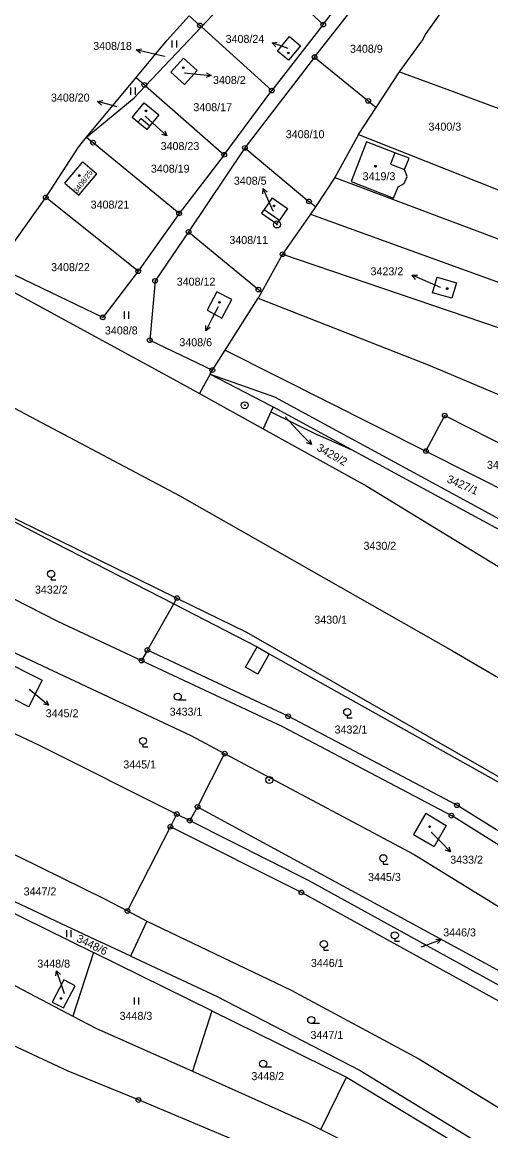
# Model space of a CAD drawing. Extents: x -593183 to -588034, y -1130415 to -1124994.
# Drawn here: x -592629 to -592529.4, y -1128913.5 to -1128677.9 of the extents above; entities that cross this region are included whole.
import ezdxf

# ---------------------------------------------------------------- set-up
doc = ezdxf.new("R2010")
doc.units = 0
for name, color, linetype in [('Vrstva 1', 7, 'Continuous'), ('Vrstva 16', 7, 'Continuous'), ('Vrstva 18', 7, 'Continuous'), ('Vrstva 19', 7, 'Continuous'), ('Vrstva 24', 7, 'Continuous'), ('Vrstva 25', 7, 'Continuous'), ('Vrstva 4', 7, 'Continuous')]:
    doc.layers.add(name, color=color, linetype=linetype)

msp = doc.modelspace()

# ---------------------------------------------------------------- linework, layer by layer
at = {"layer": 'Vrstva 1'}
for p, q in [((-592565.01, -1128678.4), (-592551.77, -1128661.06)), ((-592566.85, -1128685.3), (-592549.6, -1128663.24)), ((-592590.91, -1128678.86), (-592578.64, -1128665.83)), ((-592578.64, -1128665.83), (-592565.01, -1128678.4)), ((-592537.4, -1128672.05), (-592543.19, -1128680.31)), ((-592598.22, -1128681.71), (-592593.48, -1128676.53)), ((-592593.48, -1128676.53), (-592591.22, -1128678.58)), ((-592602.77, -1128691.45), (-592590.91, -1128678.86)), ((-592591.22, -1128678.58), (-592590.91, -1128678.86)), ((-592590.91, -1128678.86), (-592575.96, -1128692.42)), ((-592565.01, -1128678.4), (-592575.96, -1128692.42)), ((-592604.81, -1128689.67), (-592598.22, -1128681.71)), ((-592574.77, -1128684.08), (-592572.18, -1128680.97)), ((-592572.18, -1128680.97), (-592569.85, -1128682.91)), ((-592548.82, -1128688.45), (-592544.06, -1128681.91)), ((-592543.19, -1128680.31), (-592544.06, -1128681.91)), ((-592572.42, -1128685.98), (-592574.77, -1128684.08)), ((-592569.85, -1128682.91), (-592572.42, -1128685.98)), ((-592597.4, -1128688.53), (-592594.74, -1128685.56)), ((-592594.74, -1128685.56), (-592591.84, -1128688.16)), ((-592566.85, -1128685.3), (-592581.66, -1128704.6)), ((-592566.85, -1128685.3), (-592555.46, -1128694.64)), ((-592594.5, -1128691.13), (-592597.4, -1128688.53)), ((-592591.84, -1128688.16), (-592594.5, -1128691.13)), ((-592553.77, -1128696.03), (-592548.82, -1128688.45)), ((-592548.82, -1128688.45), (-592538.73, -1128692.12)), ((-592615.32, -1128702.35), (-592604.81, -1128689.67)), ((-592604.81, -1128689.67), (-592603.04, -1128691.22)), ((-592603.04, -1128691.22), (-592602.77, -1128691.45)), ((-592602.77, -1128691.45), (-592605.17, -1128694)), ((-592602.77, -1128691.45), (-592586.05, -1128706.06)), ((-592586.05, -1128706.06), (-592575.96, -1128692.42)), ((-592538.73, -1128692.12), (-592523.45, -1128697.86)), ((-592615.32, -1128702.35), (-592605.17, -1128694)), ((-592605.62, -1128698.13), (-592603.06, -1128695.05)), ((-592603.06, -1128695.05), (-592599.98, -1128697.61)), ((-592557.5, -1128701.77), (-592553.77, -1128696.03)), ((-592555.46, -1128694.64), (-592553.77, -1128696.03)), ((-592604.39, -1128699.15), (-592605.62, -1128698.13)), ((-592599.98, -1128697.61), (-592601.9, -1128699.92)), ((-592602.54, -1128700.69), (-592604.39, -1128699.15)), ((-592601.9, -1128699.92), (-592602.54, -1128700.69)), ((-592617.04, -1128704.43), (-592615.32, -1128702.35)), ((-592615.32, -1128702.35), (-592613.92, -1128703.5)), ((-592557.5, -1128701.77), (-592562.55, -1128710.89)), ((-592557.5, -1128701.77), (-592539.83, -1128708.8)), ((-592624, -1128715.14), (-592617.04, -1128704.43)), ((-592595.67, -1128718.55), (-592613.92, -1128703.5)), ((-592581.66, -1128704.6), (-592593.65, -1128722.45)), ((-592581.66, -1128704.6), (-592568.05, -1128715.98)), ((-592555.8, -1128703.33), (-592559.1, -1128711.75)), ((-592549.82, -1128705.64), (-592555.8, -1128703.33)), ((-592619.95, -1128712.12), (-592616.12, -1128707.6)), ((-592616.12, -1128707.6), (-592613.12, -1128710.14)), ((-592586.05, -1128706.06), (-592595.67, -1128718.55)), ((-592546.78, -1128706.8), (-592549.82, -1128705.64)), ((-592547.73, -1128709.22), (-592546.78, -1128706.8)), ((-592616.97, -1128714.68), (-592613.12, -1128710.14)), ((-592547.2, -1128710.68), (-592547.73, -1128709.22)), ((-592539.83, -1128708.8), (-592506.46, -1128722.05)), ((-592619.95, -1128712.12), (-592616.97, -1128714.68)), ((-592562.55, -1128710.89), (-592566.68, -1128717.13)), ((-592562.55, -1128710.89), (-592511.66, -1128730)), ((-592559.1, -1128711.75), (-592550.09, -1128715.28)), ((-592549.08, -1128712.89), (-592547.79, -1128712.18)), ((-592547.79, -1128712.18), (-592547.2, -1128710.68)), ((-592550.09, -1128715.28), (-592549.08, -1128712.89)), ((-592634.43, -1128729.78), (-592624, -1128715.14)), ((-592604.35, -1128730.83), (-592624, -1128715.14)), ((-592575.84, -1128715.21), (-592577.59, -1128717.7)), ((-592575.84, -1128715.21), (-592572.59, -1128717.5)), ((-592566.68, -1128717.13), (-592568.05, -1128715.98)), ((-592566.68, -1128717.13), (-592567.7, -1128718.67)), ((-592595.67, -1128718.55), (-592604.35, -1128730.83)), ((-592577.59, -1128717.7), (-592578.13, -1128718.46)), ((-592578.13, -1128718.46), (-592574.88, -1128720.75)), ((-592572.59, -1128717.5), (-592574.34, -1128719.99)), ((-592567.7, -1128718.67), (-592573.65, -1128727.2)), ((-592567.7, -1128718.67), (-592514.6, -1128737.95)), ((-592574.88, -1128720.75), (-592574.34, -1128719.99)), ((-592593.65, -1128722.45), (-592600.76, -1128732.89)), ((-592593.65, -1128722.45), (-592578.78, -1128734.71)), ((-592573.65, -1128727.2), (-592578.13, -1128735.25)), ((-592573.65, -1128727.2), (-592517.32, -1128746.38)), ((-592611.87, -1128740.64), (-592634.43, -1128729.78)), ((-592604.35, -1128730.83), (-592611.87, -1128740.64)), ((-592600.76, -1128732.89), (-592601.9, -1128745.48)), ((-592541.82, -1128735.39), (-592540.84, -1128732.07)), ((-592540.84, -1128732.07), (-592536.73, -1128733.32)), ((-592536.73, -1128733.32), (-592537.72, -1128736.57)), ((-592633.39, -1128733.84), (-592596.86, -1128753.74)), ((-592587.6, -1128735.2), (-592589.68, -1128739.12)), ((-592584.46, -1128736.86), (-592587.6, -1128735.2)), ((-592578.13, -1128735.25), (-592578.85, -1128736.54)), ((-592578.13, -1128735.25), (-592578.78, -1128734.71)), ((-592537.72, -1128736.57), (-592541.82, -1128735.39)), ((-592586.54, -1128740.78), (-592584.46, -1128736.86)), ((-592585.83, -1128747.56), (-592578.85, -1128736.54)), ((-592578.85, -1128736.54), (-592542.34, -1128750.84)), ((-592589.68, -1128739.12), (-592586.54, -1128740.78)), ((-592601.9, -1128745.48), (-592588.59, -1128751.84)), ((-592588.59, -1128751.84), (-592585.83, -1128747.56)), ((-592585.83, -1128747.56), (-592543.19, -1128769.03)), ((-592589.07, -1128752.68), (-592588.59, -1128751.84)), ((-592542.34, -1128750.84), (-592501.44, -1128768.19)), ((-592642.14, -1128753.84), (-592595.5, -1128778.54)), ((-592596.86, -1128753.74), (-592591.3, -1128756.82)), ((-592589.07, -1128752.68), (-592576.34, -1128759.26)), ((-592589.07, -1128752.68), (-592575.39, -1128757.5)), ((-592591.3, -1128756.82), (-592577.77, -1128764.3)), ((-592576.34, -1128759.26), (-592575.69, -1128759.61)), ((-592575.69, -1128759.61), (-592576.16, -1128760.69)), ((-592575.69, -1128759.61), (-592558.37, -1128769.07)), ((-592575.39, -1128757.5), (-592532.71, -1128780.66)), ((-592576.16, -1128760.69), (-592577.77, -1128764.3)), ((-592576.16, -1128760.69), (-592566.21, -1128765.58)), ((-592543.19, -1128769.03), (-592539.2, -1128761.5)), ((-592539.2, -1128761.5), (-592512.55, -1128775)), ((-592577.77, -1128764.3), (-592555.76, -1128776.5)), ((-592558.37, -1128769.07), (-592566.21, -1128765.58)), ((-592558.37, -1128769.07), (-592533.66, -1128782.42)), ((-592543.19, -1128769.03), (-592516.78, -1128782.4)), ((-592651.24, -1128773.27), (-592596.1, -1128800.28)), ((-592555.76, -1128776.5), (-592500.87, -1128810.07)), ((-592595.5, -1128778.54), (-592537.54, -1128811.45)), ((-592532.71, -1128780.66), (-592491.3, -1128803.52)), ((-592533.66, -1128782.42), (-592492.95, -1128804.65)), ((-592658.93, -1128786), (-592621.52, -1128805.17)), ((-592602.38, -1128811.32), (-592596.8, -1128801.52)), ((-592596.8, -1128801.52), (-592596.1, -1128800.28)), ((-592596.1, -1128800.28), (-592581.35, -1128807.51)), ((-592642.72, -1128806.29), (-592593.16, -1128829.48)), ((-592621.52, -1128805.17), (-592603.63, -1128813.55)), ((-592581.35, -1128807.51), (-592520.98, -1128842.15)), ((-592671.83, -1128809.7), (-592625.38, -1128831.52)), ((-592602.38, -1128811.32), (-592603.63, -1128813.55)), ((-592537.54, -1128811.45), (-592510.51, -1128827.31)), ((-592603.63, -1128813.55), (-592573.65, -1128827.58)), ((-592631.33, -1128814.41), (-592627.7, -1128816.25)), ((-592627.7, -1128816.25), (-592624.77, -1128817.74)), ((-592624.77, -1128817.74), (-592627.23, -1128822.61)), ((-592627.6, -1128823.35), (-592634.17, -1128820.04)), ((-592627.23, -1128822.61), (-592627.6, -1128823.35)), ((-592573.65, -1128827.58), (-592537.79, -1128846.51)), ((-592593.16, -1128829.48), (-592585.97, -1128833.31)), ((-592625.38, -1128831.52), (-592596.15, -1128846.18)), ((-592585.97, -1128833.31), (-592591.74, -1128844.64)), ((-592585.97, -1128833.31), (-592545.7, -1128854.76)), ((-592597.51, -1128848.85), (-592596.15, -1128846.18)), ((-592596.15, -1128846.18), (-592593.4, -1128847.56)), ((-592591.74, -1128844.64), (-592593.4, -1128847.56)), ((-592591.74, -1128844.64), (-592500.24, -1128894.35)), ((-592543.23, -1128845.99), (-592545.82, -1128850.5)), ((-592543.23, -1128845.99), (-592538.88, -1128848.6)), ((-592487.57, -1128877.76), (-592537.79, -1128846.51)), ((-592642.36, -1128849.02), (-592611.53, -1128864.17)), ((-592606.62, -1128866.75), (-592597.51, -1128848.85)), ((-592569.67, -1128862.82), (-592597.51, -1128848.85)), ((-592593.4, -1128847.56), (-592568.22, -1128860.19)), ((-592538.88, -1128848.6), (-592541.47, -1128853.04)), ((-592545.82, -1128850.5), (-592541.47, -1128853.04)), ((-592545.7, -1128854.76), (-592493.21, -1128887.15)), ((-592568.22, -1128860.19), (-592502.35, -1128896.51)), ((-592639.69, -1128862.87), (-592613.85, -1128875.59)), ((-592636.24, -1128862.15), (-592612.32, -1128873.39)), ((-592504.62, -1128898.68), (-592569.67, -1128862.82)), ((-592611.53, -1128864.17), (-592606.62, -1128866.75)), ((-592606.62, -1128866.75), (-592602.51, -1128868.91)), ((-592602.51, -1128868.91), (-592605.81, -1128876.1)), ((-592602.51, -1128868.91), (-592571.83, -1128883.62)), ((-592644.9, -1128875.1), (-592618.24, -1128889.09)), ((-592605.94, -1128876.37), (-592612.32, -1128873.39)), ((-592613.85, -1128875.59), (-592618.24, -1128889.09)), ((-592588.73, -1128887.96), (-592613.85, -1128875.59)), ((-592605.81, -1128876.1), (-592605.94, -1128876.37)), ((-592605.94, -1128876.37), (-592587.72, -1128884.89)), ((-592620.16, -1128881.43), (-592622.6, -1128886.11)), ((-592617.77, -1128882.69), (-592620.16, -1128881.43)), ((-592620.2, -1128887.36), (-592617.77, -1128882.69)), ((-592571.83, -1128883.62), (-592544.73, -1128898.2)), ((-592619.2, -1128900.8), (-592649.22, -1128886.8)), ((-592622.6, -1128886.11), (-592620.2, -1128887.36)), ((-592587.72, -1128884.89), (-592557.17, -1128900.66)), ((-592618.24, -1128889.09), (-592613.37, -1128891.65)), ((-592588.73, -1128887.96), (-592592.83, -1128900.78)), ((-592588.73, -1128887.96), (-592560.11, -1128902.05)), ((-592613.37, -1128891.65), (-592592.83, -1128900.78)), ((-592544.73, -1128898.2), (-592519.97, -1128913.33)), ((-592604.29, -1128906.93), (-592619.2, -1128900.8)), ((-592592.83, -1128900.78), (-592568.37, -1128911.76)), ((-592557.17, -1128900.66), (-592525.77, -1128919.8)), ((-592565.5, -1128913.19), (-592560.11, -1128902.05)), ((-592560.11, -1128902.05), (-592527.53, -1128921.66)), ((-592560.34, -1128925.33), (-592604.29, -1128906.93)), ((-592568.37, -1128911.76), (-592565.5, -1128913.19)), ((-592565.5, -1128913.19), (-592534.27, -1128928.78))]:
    msp.add_line(p, q, dxfattribs=at)
msp.add_lwpolyline([(-592486.33, -1128875.59), (-592536.62, -1128844.3), (-592572.48, -1128825.37), (-592602.38, -1128811.32)], dxfattribs=at)
at = {"layer": 'Vrstva 16'}
for p, q in [((-592572.47, -1128683.47), (-592573.06, -1128683.27)), ((-592598.73, -1128685.21), (-592601.83, -1128684.48)), ((-592594.54, -1128688.66), (-592591.85, -1128688.94)), ((-592608.9, -1128695.88), (-592610.08, -1128695.56)), ((-592602.88, -1128697.9), (-592600.49, -1128700.03)), ((-592575.65, -1128718.07), (-592576.57, -1128715.98)), ((-592540.11, -1128734.31), (-592543.38, -1128732.89)), ((-592587.33, -1128738.38), (-592588.6, -1128740.81)), ((-592573.08, -1128761.79), (-592569.61, -1128765.48)), ((-592627.52, -1128819.64), (-592625.7, -1128821.14)), ((-592542.08, -1128850.03), (-592540.06, -1128852.07)), ((-592544.2, -1128874.4), (-592542.77, -1128873.88)), ((-592619.98, -1128884.34), (-592620.7, -1128882.28))]:
    msp.add_line(p, q, dxfattribs=at)
at = {"layer": 'Vrstva 24'}
for centre, radius in [((-592591.22, -1128678.58), 0.5), ((-592591.22, -1128678.58), 0.0327), ((-592565.01, -1128678.4), 0.5), ((-592565.01, -1128678.4), 0.0327), ((-592566.85, -1128685.3), 0.5), ((-592566.85, -1128685.3), 0.0327), ((-592603.04, -1128691.22), 0.5), ((-592603.04, -1128691.22), 0.0327), ((-592575.96, -1128692.42), 0.5), ((-592575.96, -1128692.42), 0.0327), ((-592555.46, -1128694.64), 0.5), ((-592555.46, -1128694.64), 0.0327), ((-592613.92, -1128703.5), 0.5), ((-592613.92, -1128703.5), 0.0327), ((-592581.66, -1128704.6), 0.5), ((-592581.66, -1128704.6), 0.0327), ((-592586.05, -1128706.06), 0.5), ((-592586.05, -1128706.06), 0.0327), ((-592624, -1128715.14), 0.5), ((-592624, -1128715.14), 0.0327), ((-592568.05, -1128715.98), 0.5), ((-592568.05, -1128715.98), 0.0327), ((-592595.67, -1128718.55), 0.5), ((-592595.67, -1128718.55), 0.0327), ((-592593.65, -1128722.45), 0.5), ((-592574.85, -1128720.88), 0.75), ((-592574.85, -1128720.88), 0.0903), ((-592593.65, -1128722.45), 0.0327), ((-592573.65, -1128727.2), 0.5), ((-592573.65, -1128727.2), 0.0327), ((-592604.35, -1128730.83), 0.5), ((-592604.35, -1128730.83), 0.0327), ((-592600.76, -1128732.89), 0.5), ((-592600.76, -1128732.89), 0.0327), ((-592578.78, -1128734.71), 0.5), ((-592578.78, -1128734.71), 0.0327), ((-592611.87, -1128740.64), 0.5), ((-592611.87, -1128740.64), 0.0327), ((-592601.9, -1128745.48), 0.5), ((-592601.9, -1128745.48), 0.0327), ((-592588.59, -1128751.84), 0.5), ((-592588.59, -1128751.84), 0.0327), ((-592581.71, -1128759.3), 0.75), ((-592581.71, -1128759.3), 0.0903), ((-592539.2, -1128761.5), 0.5), ((-592539.2, -1128761.5), 0.0327), ((-592543.19, -1128769.03), 0.5), ((-592543.19, -1128769.03), 0.0327), ((-592596.1, -1128800.28), 0.5), ((-592596.1, -1128800.28), 0.0327), ((-592602.38, -1128811.32), 0.5), ((-592602.38, -1128811.32), 0.0327), ((-592603.63, -1128813.55), 0.5), ((-592603.63, -1128813.55), 0.0327), ((-592572.48, -1128825.37), 0.5), ((-592572.48, -1128825.37), 0.0327), ((-592585.97, -1128833.31), 0.5), ((-592585.97, -1128833.31), 0.0327), ((-592576.49, -1128838.94), 0.75), ((-592576.49, -1128838.94), 0.0903), ((-592591.74, -1128844.64), 0.5), ((-592536.62, -1128844.3), 0.5), ((-592536.62, -1128844.3), 0.0327), ((-592596.15, -1128846.18), 0.5), ((-592596.15, -1128846.18), 0.0327), ((-592591.74, -1128844.64), 0.0327), ((-592537.79, -1128846.51), 0.5), ((-592537.79, -1128846.51), 0.0327), ((-592597.51, -1128848.85), 0.5), ((-592597.51, -1128848.85), 0.0327), ((-592593.4, -1128847.56), 0.5), ((-592593.4, -1128847.56), 0.0327), ((-592569.67, -1128862.82), 0.5), ((-592569.67, -1128862.82), 0.0327), ((-592606.62, -1128866.75), 0.5), ((-592606.62, -1128866.75), 0.0327), ((-592604.29, -1128906.93), 0.5), ((-592604.29, -1128906.93), 0.0327)]:
    msp.add_circle(centre, radius, dxfattribs=at)
at = {"layer": 'Vrstva 25'}
for p, q in [((-592597.18, -1128681.76), (-592597.18, -1128683.26)), ((-592596.16, -1128683.26), (-592596.16, -1128681.76)), ((-592601.83, -1128684.48), (-592604.75, -1128683.8)), ((-592573.06, -1128683.27), (-592575.9, -1128682.3)), ((-592591.85, -1128688.94), (-592588.87, -1128689.25)), ((-592605.97, -1128691.8), (-592605.97, -1128693.3)), ((-592604.95, -1128693.3), (-592604.95, -1128691.8)), ((-592610.08, -1128695.56), (-592612.97, -1128694.77)), ((-592600.49, -1128700.03), (-592598.25, -1128702.03)), ((-592576.57, -1128715.98), (-592577.78, -1128713.23)), ((-592543.38, -1128732.89), (-592546.13, -1128731.69)), ((-592607.36, -1128739.41), (-592607.36, -1128740.91)), ((-592606.34, -1128740.91), (-592606.34, -1128739.41)), ((-592588.6, -1128740.81), (-592589.99, -1128743.47)), ((-592569.61, -1128765.48), (-592567.55, -1128767.66)), ((-592622.86, -1128795.88), (-592622.86, -1128796.38)), ((-592622.86, -1128796.38), (-592621.84, -1128796.38)), ((-592625.7, -1128821.14), (-592623.38, -1128823.05)), ((-592594.18, -1128821.97), (-592595.93, -1128821.97)), ((-592559.92, -1128825.25), (-592559.92, -1128825.75)), ((-592559.92, -1128825.75), (-592558.9, -1128825.75)), ((-592603.34, -1128831.38), (-592603.34, -1128831.88)), ((-592603.34, -1128831.88), (-592602.32, -1128831.88)), ((-592540.06, -1128852.07), (-592537.95, -1128854.2)), ((-592552.25, -1128856.31), (-592552.25, -1128856.81)), ((-592552.25, -1128856.81), (-592551.23, -1128856.81)), ((-592619.6, -1128870.86), (-592619.6, -1128872.36)), ((-592618.58, -1128872.36), (-592618.58, -1128870.86)), ((-592549.81, -1128872.69), (-592549.81, -1128873.19)), ((-592564.89, -1128874.56), (-592564.89, -1128875.06)), ((-592564.89, -1128875.06), (-592563.87, -1128875.06)), ((-592549.81, -1128873.19), (-592548.79, -1128873.19)), ((-592542.77, -1128873.88), (-592539.95, -1128872.85)), ((-592620.7, -1128882.28), (-592621.69, -1128879.45)), ((-592605.23, -1128885.14), (-592605.23, -1128886.64)), ((-592604.21, -1128886.64), (-592604.21, -1128885.14)), ((-592565.82, -1128890.68), (-592567.57, -1128890.68)), ((-592576.04, -1128899.98), (-592577.79, -1128899.98))]:
    msp.add_line(p, q, dxfattribs=at)
for points in [[(-592603.89, -1128684.51), (-592604.75, -1128683.8), (-592603.66, -1128683.54)], [(-592575.11, -1128683.1), (-592575.9, -1128682.3), (-592574.79, -1128682.15)], [(-592589.81, -1128688.65), (-592588.87, -1128689.25), (-592589.91, -1128689.64)], [(-592612.14, -1128695.52), (-592612.97, -1128694.77), (-592611.88, -1128694.55)], [(-592598.66, -1128700.99), (-592598.25, -1128702.03), (-592599.33, -1128701.73)], [(-592577.83, -1128714.35), (-592577.78, -1128713.23), (-592576.92, -1128713.95)], [(-592545.41, -1128732.55), (-592546.13, -1128731.69), (-592545.01, -1128731.63)], [(-592589.08, -1128742.81), (-592589.99, -1128743.47), (-592589.97, -1128742.35)], [(-592567.87, -1128766.59), (-592567.55, -1128767.66), (-592568.6, -1128767.28)], [(-592623.84, -1128822.03), (-592623.38, -1128823.05), (-592624.47, -1128822.8)], [(-592538.3, -1128853.14), (-592537.95, -1128854.2), (-592539.01, -1128853.84)], [(-592541.06, -1128872.73), (-592539.95, -1128872.85), (-592540.72, -1128873.67)], [(-592621.83, -1128880.56), (-592621.69, -1128879.45), (-592620.89, -1128880.23)]]:
    msp.add_lwpolyline(points, dxfattribs=at)
for centre, radius in [((-592572.44, -1128684.43), 0.175), ((-592572.44, -1128684.43), 0.15), ((-592594.76, -1128687.57), 0.175), ((-592594.76, -1128687.57), 0.15), ((-592602.7, -1128696.75), 0.175), ((-592602.7, -1128696.75), 0.15), ((-592553.91, -1128708.5), 0.175), ((-592553.91, -1128708.5), 0.15), ((-592616.87, -1128710.48), 0.175), ((-592616.87, -1128710.48), 0.15), ((-592575.5, -1128716.93), 0.175), ((-592575.5, -1128716.93), 0.15), ((-592538.68, -1128734.5), 0.175), ((-592538.68, -1128734.5), 0.15), ((-592587.07, -1128737.42), 0.175), ((-592587.07, -1128737.42), 0.15), ((-592622.86, -1128795.13), 0.75), ((-592595.93, -1128821.22), 0.75), ((-592559.92, -1128824.5), 0.75), ((-592603.34, -1128830.63), 0.75), ((-592542.42, -1128848.86), 0.175), ((-592542.42, -1128848.86), 0.15), ((-592552.25, -1128855.56), 0.75), ((-592549.81, -1128871.94), 0.75), ((-592564.89, -1128873.81), 0.75), ((-592620.75, -1128885.35), 0.175), ((-592620.75, -1128885.35), 0.15), ((-592567.57, -1128889.93), 0.75), ((-592577.79, -1128899.23), 0.75)]:
    msp.add_circle(centre, radius, dxfattribs=at)
at = {"layer": 'Vrstva 4'}
for p, q in [((-592604.39, -1128699.15), (-592603.75, -1128698.38)), ((-592603.75, -1128698.38), (-592601.9, -1128699.92)), ((-592549.82, -1128705.64), (-592550.75, -1128708.07)), ((-592550.75, -1128708.07), (-592547.73, -1128709.22)), ((-592577.59, -1128717.7), (-592574.34, -1128719.99)), ((-592590.02, -1128754.44), (-592591.3, -1128756.82)), ((-592589.07, -1128752.68), (-592590.02, -1128754.44)), ((-592651.24, -1128773.27), (-592622.2, -1128788.44)), ((-592622.2, -1128788.44), (-592596.8, -1128801.52)), ((-592596.8, -1128801.52), (-592579.07, -1128810.65)), ((-592581.55, -1128814.97), (-592579.07, -1128810.65)), ((-592579.07, -1128810.65), (-592576.48, -1128812.11)), ((-592576.48, -1128812.11), (-592578.92, -1128816.42)), ((-592576.48, -1128812.11), (-592522.27, -1128842.49)), ((-592578.92, -1128816.42), (-592581.55, -1128814.97))]:
    msp.add_line(p, q, dxfattribs=at)

# ---------------------------------------------------------------- texts
at = {"layer": 'Vrstva 16'}
for s, p in [('3408/24', (-592585.77, -1128682.3)), ('3408/18', (-592613.91, -1128683.8)), ('3408/2', (-592588.45, -1128691.03)), ('3408/20', (-592622.89, -1128694.77)), ('3408/23', (-592599.58, -1128705.07)), ('3408/5', (-592584.01, -1128712.44)), ('3423/2', (-592554.97, -1128731.69)), ('3408/6', (-592595.6, -1128746.76)), ('3426/5', (-592530.22, -1128772.82)), ('3445/2', (-592623.99, -1128825.6)), ('3433/2', (-592538.03, -1128856.71)), ('3446/3', (-592539.52, -1128872.17)), ('3448/8', (-592625.78, -1128878.8))]:
    msp.add_text(s, height=1.7, dxfattribs=at).set_placement(p)
msp.add_text('3429/2', height=1.7, rotation=330.3077, dxfattribs=at).set_placement((-592566.57, -1128768.81))
at = {"layer": 'Vrstva 18'}
for s, height, p in [('3408/9', 1.7, (-592559.33, -1128684.4)), ('3408/18', 0.1, (-592598.73, -1128685.21)), ('3408/20', 0.1, (-592608.9, -1128695.88)), ('3408/17', 1.7, (-592592.62, -1128696.81)), ('3408/10', 1.7, (-592572.98, -1128702.55)), ('3400/3', 1.7, (-592542.65, -1128700.94)), ('3408/19', 1.7, (-592601.65, -1128709.87)), ('3408/21', 1.7, (-592614.45, -1128717.51)), ('3408/11', 1.7, (-592584.97, -1128725.03)), ('3408/22', 1.7, (-592622.85, -1128730.8)), ('3408/12', 1.7, (-592596.16, -1128733.88)), ('3408/8', 1.7, (-592611.42, -1128744.25)), ('3429/2', 0.1, (-592573.08, -1128761.79)), ('3430/2', 1.7, (-592556.46, -1128790.01)), ('3432/2', 1.7, (-592626.29, -1128799.32)), ('3430/1', 1.7, (-592566.92, -1128805.72)), ('3433/1', 1.7, (-592597.66, -1128825.27)), ('3432/1', 1.7, (-592562.61, -1128829.06)), ('3445/1', 1.7, (-592607.51, -1128836.48)), ('3445/3', 1.7, (-592555.49, -1128860.39)), ('3447/2', 1.7, (-592628.69, -1128863.46)), ('3446/3', 0.2, (-592544.2, -1128874.4)), ('3446/1', 1.7, (-592567.64, -1128878.66)), ('3448/3', 1.7, (-592608.3, -1128889.9)), ('3447/1', 1.7, (-592567.73, -1128893.96)), ('3448/2', 1.7, (-592580.29, -1128902.71))]:
    msp.add_text(s, height=height, dxfattribs=at).set_placement(p)
for s, rotation, p in [('3427/1', 336.1589, (-592538.9, -1128775.59)), ('3448/6', 333.7621, (-592617.62, -1128873.18))]:
    msp.add_text(s, height=1.7, rotation=rotation, dxfattribs=at).set_placement(p)
at = {"layer": 'Vrstva 19'}
for s, height, p in [('3408/24', 0.1, (-592572.47, -1128683.47)), ('3408/2', 0.1, (-592594.54, -1128688.66)), ('3408/23', 0.1, (-592602.88, -1128697.9)), ('3419/3', 1.7, (-592556.65, -1128711.48)), ('3408/5', 0.1, (-592575.65, -1128718.07)), ('3423/2', 0.1, (-592540.11, -1128734.31)), ('3408/6', 0.1, (-592587.33, -1128738.38)), ('3445/2', 0.1, (-592627.52, -1128819.64)), ('3433/2', 0.1, (-592542.08, -1128850.03)), ('3448/8', 0.1, (-592619.98, -1128884.34))]:
    msp.add_text(s, height=height, dxfattribs=at).set_placement(p)
msp.add_text('3408/25', height=1.14, rotation=53.3742, dxfattribs=at).set_placement((-592617.33, -1128714.42))

doc.saveas('drawing.dxf')
